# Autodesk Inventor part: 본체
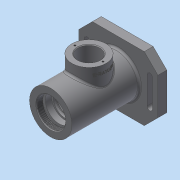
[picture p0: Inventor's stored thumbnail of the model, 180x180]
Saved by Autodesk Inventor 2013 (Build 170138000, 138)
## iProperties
Created: 2017-10
Part Number: 본체
Material: 일반
Document SubType Name: Modeling
Designer: Administrator
Density: 1 g/cm^3
Author: Administrator
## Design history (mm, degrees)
sketch "스케치2"
  geometry: L1 (0, 0)-(99, 0); L2 (0, 0)-(0, 31); L3 (0, 31)-(99, 31); L4 (99, 31)-(99, 0)
  constraints: 8 end point, 3 perpendicular, 1 horizontal
  dimensions: "d0" = 99 distance of L1.start L1.end; "d2" = 62 diameter of L3 L1
revolve "회전1" sketch "스케치2" stored, may be unused: angle "d3" = 90 deg
sketch "스케치3"
  geometry: L1 (38, -47)-(-38, -47); L2 (-58, -27)-(-58, 27); L3 (-38, 47)-(38, 47); L4 (58, 27)-(58, -27); L5 (0, 0)-(-31, 0); L6 (0, 0)-(0, -31); L7 (58, -27)-(38, -47); L8 (-38, -47)-(-58, -27); L9 (-58, 27)-(-38, 47); L10 (58, 27)-(38, 47); L11 (42, -20)-(42, 20); L12 (50, -20)-(50, 20); L13 (-42, -20)-(-42, 20); L14 (-50, -20)-(-50, 20); A1 r 31 centre (0, 0) between (-31, 0) and (0, -31) reference; A2 r 4 centre (46, 20) between (50, 20) and (42, 20); A3 r 4 centre (46, -20) between (42, -20) and (50, -20); A4 r 4 centre (-46, -20) between (-50, -20) and (-42, -20); A5 r 4 centre (-46, 20) between (-42, 20) and (-50, 20); 4 further points
  constraints: 28 end point, 10 point on circle, 8 point on line, 6 symmetric about line, 4 centre point, 3 parallel, 3 perpendicular, 3 tangent, 1 equal radius, 1 horizontal, 5 other
  dimensions: "d5" = 116 distance between parallel lines of L2 L4; "d7" = 94 distance between parallel lines of L3 L1; "d8" = 20 distance of L4.end point (58, -47); "d9" = 20 distance of L1.start point (58, -47) (= d8); "d10" = 20 distance of L1.end point (-58, -47) (= d8); "d11" = 20 distance of L2.start point (-58, -47) (= d10); "d12" = 20 distance of L2.end point (-58, 47) (= d8); "d13" = 20 distance of L3.start point (-58, 47) (= d12); "d14" = 20 distance of L4.start point (58, 47) (= d8); "d15" = 20 distance of L3.end point (58, 47) (= d14); "d16" = 8 diameter of A3; "d17" = 40 distance of A2.centre A3.centre; "d18" = 92 distance of A5.centre A2.centre
extrude "돌출1" join sketch "스케치3" distance "d19" = 13; taper "d20" = 0 deg
sketch "스케치4"
  geometry: C1 r 35 at (0, 0); 1 further point
  constraints: 1 centre point, 1 coincident
  dimensions: "d21" = 70 diameter of C1
extrude "돌출2" join sketch "스케치4" distance "d23" = 3; taper "d24" = 0 deg
sketch "스케치5"
  geometry: L1 (0, -31)-(0, 31) reference; L2 (0, 31)-(99, 31) reference; L3 (99, 31)-(99, 47) reference; L4 (99, 47)-(112, 47) reference; L5 (112, 47)-(112, 35) reference; L6 (112, 35)-(115, 35) reference; L7 (115, 35)-(115, -35) reference; L8 (115, -35)-(112, -35) reference; L9 (112, -35)-(112, -47) reference; L10 (112, -47)-(99, -47) reference; L11 (99, -47)-(99, -31) reference; L12 (99, -31)-(0, -31) reference; L13 (0, 0)-(115, 0); L14 (0, -31)-(0, 31) reference; L15 (0, 21)-(9, 21); L16 (9, 21)-(9, 24); L17 (9, 24)-(12, 24); L18 (12, 24)-(12, 20); L19 (12, 20)-(21, 20); L20 (21, 20)-(21, 17.5); L21 (21, 17.5)-(24.25, 17.5); L22 (24.25, 17.5)-(24.25, 18.5); L23 (24.25, 18.5)-(26, 18.5); L24 (26, 18.5)-(26, 17.5); L25 (26, 17.5)-(36, 17.5); L26 (37, 18.5)-(37, 23); L27 (40, 26)-(72, 26); L28 (75, 23)-(75, 18.5); L29 (76, 17.5)-(85.7, 17.5); L30 (86, 17.2)-(86, 16.5); L31 (86, 16.5)-(88, 16.5); L32 (91, 13.5)-(91, 10); L33 (91, 10)-(93.7, 10); L34 (93.7, 10)-(93.7, 12.2); L35 (94, 12.5)-(100.3, 12.5); L36 (101, 12.904)-(101, 14.022); L37 (102.818, 16.779)-(115, 22); L38 (100.3, 12.5)-(101, 12.904); L39 (75, 18.5)-(76, 17.5); L40 (36, 17.5)-(37, 18.5); A1 r 3 centre (88, 13.5) between (91, 13.5) and (88, 16.5); A2 r 3 centre (104, 14.022) between (102.818, 16.779) and (101, 14.022); A3 r 0.3 centre (85.7, 17.2) between (86, 17.2) and (85.7, 17.5); A4 r 0.3 centre (94, 12.2) between (94, 12.5) and (93.7, 12.2); A5 r 3 centre (40, 23) between (40, 26) and (37, 23); A6 r 3 centre (72, 23) between (75, 23) and (72, 26); 9 further points
  constraints: 54 end point, 20 point on line, 15 parallel, 12 point on circle, 12 tangent, 7 perpendicular, 6 centre point, 3 equal radius, 1 midpoint
  dimensions: "d25" = 42 diameter of L15 L13; "d27" = 48 diameter of L17 L13; "d28" = 40 diameter of L19 L13; "d29" = 35 diameter of L21 L13; "d30" = 37 diameter of L23 L13; "d31" = 35 diameter of L25 L13; "d32" = 52 diameter of L27 L13; "d33" = 35 diameter of L29 L13; "d34" = 33 diameter of L31 L13; "d35" = 20 diameter of L33 L13; "d36" = 25 diameter of L35 L13; "d37" = 32 diameter of point (101, 16) L13; "d38" = 44 diameter of L37.end L13; "d39" = 12 distance between parallel lines of L18 L1; "d40" = 3 distance between parallel lines of L18 L16; "d41" = 21 distance between parallel lines of L20 L1; "d42" = 26 distance between parallel lines of L1 L24; "d43" = 1.75 distance between parallel lines of L24 L22; "d44" = 60 distance between parallel lines of L30 L24; "d45" = 5 distance between parallel lines of L32 L30; "d46" = 14 distance between parallel lines of L36 L7; "d47" = 7.3 distance between parallel lines of L34 L36; "d48" = 11 distance between parallel lines of L28 L30; "d49" = 11 distance between parallel lines of L24 L26; "d51" = 3 radius of A1; "d52" = 0.3 radius of A3; "d53" = 0.7 distance of L35.end point (101, 12.5); "d54" = 30 deg angle of L35 L38; "d55" = 1 distance of L28.end point (75, 17.5); "d56" = 1 distance of L29.start point (75, 17.5) (= d55); "d57" = 1 distance of L25.end point (37, 17.5) (= d55); "d58" = 1 distance of L26.start point (37, 17.5) (= d57); "d59" = 3 radius of A5
revolve "회전2" sketch "스케치5" stored, may be unused: angle "d50" = 90 deg
feature "스레드1" dims "d60" = 10, "d61" = 0
chamfer "모따기1" distance "d62" = 1; stored, may be unused: second distance "d63" = 2, angle "d64" = 45 deg
node "작업 평면2"
sketch "스케치6"
  geometry: L1 (0, 0)-(0, 115); L2 (-22, 115)-(22, 115) reference; L3 (31, 0)-(-31, 0) reference; C1 r 25 at (0, 56)
  constraints: 2 end point, 1 centre point, 1 midpoint, 1 point on line
  dimensions: "d91" = 50 diameter of C1; "d93" = 56 distance from line of L3 C1.centre
extrude "돌출3" join sketch "스케치6" stored distance "d68" = 10; taper "d69" = 0 deg
fillet "모깎기1" dims "d86" = 3
sketch "스케치10"
  geometry: C1 r 25 at (0, 0) reference; C2 r 16 at (0, 0); 1 further point
  constraints: 1 centre point, 1 coincident
  dimensions: "d94" = 32 diameter of C2
extrude "돌출5" cut sketch "스케치10" stored distance "d96" = 10; taper "d97" = 0 deg
sketch "스케치11" dims "d98" = 41
  geometry: L1 (0, 0)-(20.5, 0); C1 r 25 at (0, 0) reference; 2 further points
  constraints: 2 coincident, 2 end point, 1 horizontal, 1 horizontal alignment, 2 other
hole "구멍2" sketch "스케치11" at (20.5, 0) diameter "d100" = 2.459; stored, may be unused: countersink angle "d104" = 90 deg, drill point angle "d106" = 118 deg; dims "d101" = 6, "d102" = 4, "d103" = 2, "d105" = 8
node "작업 평면4"
sketch "스케치12"
  geometry: L1 (-15.909, -7.749)-(15.909, -7.749); L2 (15.909, -7.749)-(15.909, -12.251); L3 (15.909, -12.251)-(-15.909, -12.251); L4 (-15.909, -12.251)-(-15.909, -7.749); L5 (-15.909, -10)-(15.909, -10); L6 (0, -12.251)-(0, -7.749); L7 (-56, -78)-(-56, -16) reference; L8 (-25, 0)-(25, 0) reference; 1 further point
  constraints: 4 end point, 4 midpoint, 2 other
  dimensions: "d110" = 56 distance between parallel lines of L6 L7; "d111" = 10 distance between parallel lines of L5 L8
feature "엠보싱1" sketch "스케치12" dims "d0" = 99, "d2" = 62, "d12" = 20 (= d8), "d112" = 0.5, "d113" = 0
fillet "모깎기2" dims "d114" = 3
chamfer "모따기2" distance "d115" = 1; stored, may be unused: second distance "d116" = 2, angle "d117" = 45 deg
node "솔리드1"
pattern_circular "원형 패턴2" dims angle "d108" = 360 deg
node "절단 모서리 투영1"
other parameters: "d65" = 47
